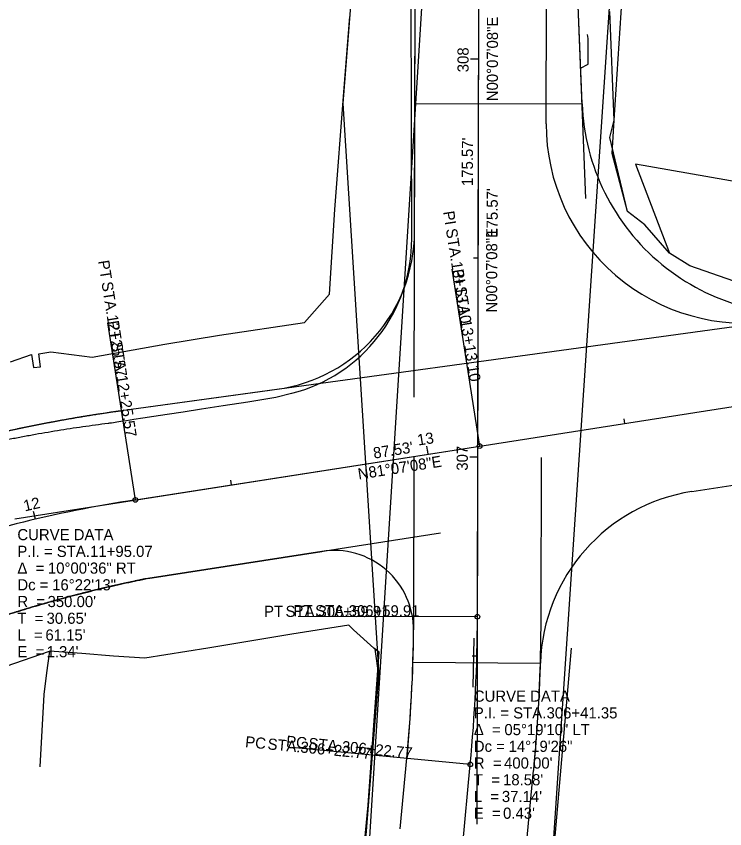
# Model space of a CAD drawing. Extents: x 219353 to 221640, y 361458 to 364236.
# Drawn here: x 220456 to 220633.9, y 362065.1 to 362269.2 of the extents above; entities that cross this region are included whole.
import ezdxf

# ---------------------------------------------------------------- set-up
doc = ezdxf.new("R2010")
doc.units = 0
for name, color, linetype in [('Default', 7, 'Continuous'), ('DR_P_Cells', 7, 'Continuous'), ('DR_P_GenericNode', 7, 'Continuous'), ('DR_X_Cells', 7, 'Continuous'), ('DR_X_GenericNode', 7, 'Continuous'), ('DR_X_Storm_Sewer', 7, 'Continuous'), ('DT_X_Contour_Major', 7, 'Continuous'), ('DT_X_Contour_Minor', 7, 'Continuous'), ('DT_X_Terrain_Boundary', 7, 'Continuous'), ('SC_ProfileRun1', 7, 'Continuous'), ('SC_ProfileRun2', 7, 'Continuous'), ('SC_ProfileRun3', 7, 'Continuous'), ('SC_Scratch1', 7, 'Continuous'), ('UT_X_San_Storm_Line', 7, 'Continuous'), ('UT_X_Sanitary_Cells', 7, 'Continuous')]:
    doc.layers.add(name, color=color, linetype=linetype)

msp = doc.modelspace()

# ---------------------------------------------------------------- linework, layer by layer
at = {"layer": 'Default'}
for p, q in [((220606.11, 362243.12), (220684.52, 363442.47)), ((220589.94, 362047.45), (220608.12, 362317.78)), ((220605.68, 362234.69), (220606.11, 362243.12)), ((220609.47, 362220.11), (220605.68, 362234.69)), ((220718.01, 362213.16), (220611.49, 362232.06)), ((220611.49, 362232.06), (220620.05, 362209.64)), ((220613.84, 362216.77), (220609.47, 362220.11)), ((220620.05, 362209.64), (220613.84, 362216.77))]:
    msp.add_line(p, q, dxfattribs=at)
for points in [[(220418.89, 362155.61), (220419.93, 362155.94), (220422, 362156.61), (220425.12, 362157.57), (220428.25, 362158.5), (220431.39, 362159.41), (220434.53, 362160.29), (220437.68, 362161.14), (220440.84, 362161.96), (220444, 362162.76), (220447.17, 362163.53), (220450.35, 362164.27), (220453.53, 362164.98), (220456.72, 362165.67), (220459.91, 362166.33), (220463.11, 362166.95), (220466.31, 362167.56), (220469.52, 362168.13), (220472.73, 362168.67), (220475.95, 362169.19), (220479.17, 362169.68), (220481.32, 362169.98), (220482.39, 362170.13)], [(220488.46, 362127.86), (220487.52, 362127.67), (220485.66, 362127.29), (220482.86, 362126.68), (220480.08, 362126.06), (220477.3, 362125.41), (220474.52, 362124.73), (220471.76, 362124.03), (220469, 362123.31), (220466.25, 362122.57), (220463.5, 362121.8), (220460.77, 362121.01), (220458.04, 362120.19), (220455.32, 362119.35), (220452.61, 362118.49), (220449.91, 362117.61), (220447.21, 362116.7), (220444.53, 362115.77), (220441.85, 362114.81), (220439.18, 362113.84), (220436.53, 362112.84), (220434.76, 362112.15), (220433.88, 362111.81)]]:
    msp.add_open_spline(points, degree=3, dxfattribs=at)
at = {"layer": 'DR_X_Cells'}
for p, q in [((220572.38, 362161.22), (220565.44, 362205.68)), ((220485.9, 362147.7), (220478.95, 362192.16)), ((220571.8, 362118.35), (220526.8, 362118.44)), ((220570.01, 362081.26), (220525.21, 362085.53))]:
    msp.add_line(p, q, dxfattribs=at)
for centre in [(220572.38, 362161.22), (220485.9, 362147.7), (220571.8, 362118.35), (220570.01, 362081.26)]:
    msp.add_circle(centre, 0.6, dxfattribs=at)
at = {"layer": 'DR_X_GenericNode'}
for p, q in [((220631.67, 363446.41), (220538.01, 362247.29)), ((220541.47, 362010.88), (220631.67, 363446.41)), ((220555.31, 362213.3), (220555.17, 362293.95)), ((220589.06, 362242.18), (220589.17, 362293.88)), ((220606.11, 362243.12), (220605.04, 362270.37)), ((220538.01, 362247.29), (220547.06, 362103.67)), ((220605.08, 362238.74), (220606.11, 362243.12)), ((220609.47, 362220.11), (220605.08, 362238.74)), ((220613.84, 362216.77), (220609.47, 362220.11)), ((220620.05, 362209.64), (220613.84, 362216.77)), ((220625.13, 362206.46), (220620.05, 362209.64)), ((220636.18, 362202.62), (220625.13, 362206.46)), ((220521.18, 362173.46), (220525.15, 362174.47)), ((220625.65, 362149.8), (220725.47, 362165.4)), ((220532.69, 362134.77), (220488.99, 362127.94)), ((220547.06, 362103.67), (220546.11, 362110.22)), ((220589.94, 362047.45), (220595.41, 362110.45)), ((220547.06, 362103.67), (220546.95, 362107.22)), ((220543.46, 362058.41), (220547.06, 362103.67)), ((220552.39, 362065.09), (220554.08, 362082.78)), ((220584.25, 362062.06), (220585.93, 362079.75))]:
    msp.add_line(p, q, dxfattribs=at)
for centre, radius, start, end in [((220639.06, 362242.08), 50, 179.8811, 278.8811), ((220515.31, 362213.24), 40, 284.2423, 0.0978), ((220632.6, 362105.34), 45, 98.8811, 178.2805), ((220535.78, 362115.01), 20, 359.3445, 98.8811), ((220539.93, 361801.9), 330, 98.8811, 98.9741), ((220171.81, 362119.18), 384, 354.5615, 359.3445), ((220171.81, 362119.18), 416, 354.5615, 358.2805)]:
    msp.add_arc(centre, radius, start, end, dxfattribs=at)
msp.add_open_spline([(220419.33, 362154.32), (220420.36, 362154.62), (220422.43, 362155.24), (220425.53, 362156.12), (220428.63, 362156.98), (220431.75, 362157.81), (220434.87, 362158.61), (220437.99, 362159.39), (220441.12, 362160.14), (220444.26, 362160.86), (220447.4, 362161.56), (220450.54, 362162.22), (220453.69, 362162.86), (220456.85, 362163.47), (220460.01, 362164.06), (220463.17, 362164.61), (220466.34, 362165.14), (220469.51, 362165.64), (220472.68, 362166.12), (220475.86, 362166.56), (220479.03, 362166.98), (220481.16, 362167.24), (220521.18, 362173.46)], degree=3, dxfattribs=at)
at = {"layer": 'DT_X_Contour_Major'}
for p, q in [((220571.7, 362066.21), (220572.38, 362396.56)), ((220571.7, 362066.21), (220572.17, 362293.91)), ((220571.8, 362118.35), (220572.17, 362293.91)), ((220571.8, 362118.35), (220572.17, 362293.91)), ((220572.38, 362161.22), (221144.38, 362250.6)), ((220572.38, 362161.22), (221144.38, 362250.6)), ((220455.61, 362142.97), (220572.38, 362161.22)), ((220485.9, 362147.7), (220572.38, 362161.22)), ((220485.9, 362147.7), (220572.38, 362161.22)), ((220570.71, 362100.69), (220570.95, 362112.98)), ((220552.88, 361901.39), (220570.01, 362081.26))]:
    msp.add_line(p, q, dxfattribs=at)
for centre, radius, start, end in [((220539.93, 361801.9), 350, 98.8811, 108.8911), ((220539.93, 361801.9), 350, 98.8811, 108.8911), ((220171.81, 362119.18), 400, 354.5615, 359.8811), ((220171.81, 362119.18), 400, 354.5615, 359.8811)]:
    msp.add_arc(centre, radius, start, end, dxfattribs=at)
at = {"layer": 'DT_X_Contour_Minor'}
for p, q in [((220482.39, 362170.13), (221640, 362328.87)), ((220555.92, 362173.47), (220556.17, 362293.95)), ((220555.92, 362173.47), (220556.17, 362293.95)), ((220556.01, 362215.03), (220556.17, 362293.95)), ((220556.01, 362215.03), (220556.17, 362293.95)), ((220556.01, 362215.03), (220556.17, 362293.95)), ((220599.02, 362223.38), (220596.25, 362293.86)), ((220598.09, 362247.17), (220596.25, 362293.86)), ((220598.09, 362247.17), (220596.25, 362293.86)), ((220556.07, 362247.25), (220598.09, 362247.17)), ((220571.8, 362118.35), (220572.07, 362247.22)), ((220482.39, 362170.13), (220521.44, 362175.49)), ((220482.39, 362170.13), (220521.44, 362175.49)), ((220482.39, 362170.13), (220521.44, 362175.49)), ((220482.39, 362170.13), (220519.63, 362175.24)), ((220625.65, 362149.8), (220725.47, 362165.4)), ((220625.65, 362149.8), (220725.47, 362165.4)), ((220555.8, 362118.38), (220555.89, 362158.44)), ((220555.8, 362118.38), (220555.89, 362158.44)), ((220587.8, 362118.31), (220587.89, 362158.38)), ((220587.8, 362118.31), (220587.89, 362158.38)), ((220488.99, 362127.94), (220562.52, 362139.43)), ((220488.99, 362127.94), (220532.69, 362134.77)), ((220532.69, 362134.77), (220488.99, 362127.94)), ((220378.74, 362079.82), (220464.36, 362109.73)), ((220555.61, 362106.94), (220587.62, 362106.69)), ((220552.39, 362065.09), (220554.08, 362082.78)), ((220552.39, 362065.09), (220554.08, 362082.78)), ((220552.39, 362065.09), (220554.08, 362082.78)), ((220552.39, 362065.09), (220554.08, 362082.78)), ((220584.25, 362062.06), (220585.93, 362079.75)), ((220584.25, 362062.06), (220585.93, 362079.75)), ((220584.25, 362062.06), (220585.93, 362079.75)), ((220584.25, 362062.06), (220585.93, 362079.75))]:
    msp.add_line(p, q, dxfattribs=at)
for points in [[(220454.55, 362182.38), (220459.81, 362184.23), (220460.35, 362180.94), (220462.07, 362181.12), (220461.66, 362184.35), (220464.67, 362184.89), (220475.07, 362183.58), (220493.27, 362186.84), (220507.06, 362189.07), (220528.39, 362192.25), (220534.64, 362199.36), (220536.02, 362220.62), (220538.22, 362250.11), (220539.75, 362269.08)], [(220542.63, 362052.8), (220544.35, 362071.05), (220545.67, 362089.98), (220547.11, 362109.41), (220545.79, 362110.48), (220540.64, 362115.08), (220539.5, 362116.23), (220525.19, 362113.93), (220504.07, 362110.45), (220488.27, 362107.93), (220480.39, 362108.46), (220472.41, 362109.12), (220464.36, 362109.73), (220463.61, 362104.26), (220462.9, 362098.83), (220461.92, 362080.65)]]:
    msp.add_lwpolyline(points, dxfattribs=at)
for centre, radius, start, end in [((220653.05, 362249.33), 55, 182.2506, 278.8811), ((220653.05, 362249.33), 55, 182.2506, 278.8811), ((220516.01, 362215.12), 40, 277.8079, 359.8811), ((220516.01, 362215.12), 40, 277.8079, 359.8811), ((220516.01, 362215.12), 40, 277.8079, 359.8811), ((220632.6, 362105.34), 45, 98.8811, 178.2805), ((220632.6, 362105.34), 45, 98.8811, 178.2805), ((220535.78, 362115.01), 20, 359.3445, 98.8811), ((220535.78, 362115.01), 20, 359.3445, 98.8811), ((220539.93, 361801.9), 330, 98.8811, 98.9741), ((220539.93, 361801.9), 330, 98.8811, 98.9741), ((220539.93, 361801.9), 330, 98.8811, 98.9741), ((220171.81, 362119.18), 384, 354.5615, 359.8811), ((220171.81, 362119.18), 384, 354.5615, 359.8811), ((220171.81, 362119.18), 400, 358.2296, 359.8811), ((220171.81, 362119.18), 416, 354.5615, 359.8811), ((220171.81, 362119.18), 416, 354.5615, 359.8811), ((220171.81, 362119.18), 384, 354.5615, 359.3445), ((220171.81, 362119.18), 384, 354.5615, 359.3445), ((220171.81, 362119.18), 416, 354.5615, 358.2805), ((220171.81, 362119.18), 416, 354.5615, 358.2805)]:
    msp.add_arc(centre, radius, start, end, dxfattribs=at)
for points in [[(220418.89, 362155.61), (220419.93, 362155.94), (220422, 362156.61), (220425.12, 362157.57), (220428.25, 362158.5), (220431.39, 362159.41), (220434.53, 362160.29), (220437.68, 362161.14), (220440.84, 362161.96), (220444, 362162.76), (220447.17, 362163.53), (220450.35, 362164.27), (220453.53, 362164.98), (220456.72, 362165.67), (220459.91, 362166.33), (220463.11, 362166.95), (220466.31, 362167.56), (220469.52, 362168.13), (220472.73, 362168.67), (220475.95, 362169.19), (220479.17, 362169.68), (220481.32, 362169.98), (220482.39, 362170.13)], [(220418.89, 362155.61), (220419.93, 362155.94), (220422, 362156.61), (220425.12, 362157.57), (220428.25, 362158.5), (220431.39, 362159.41), (220434.53, 362160.29), (220437.68, 362161.14), (220440.84, 362161.96), (220444, 362162.76), (220447.17, 362163.53), (220450.35, 362164.27), (220453.53, 362164.98), (220456.72, 362165.67), (220459.91, 362166.33), (220463.11, 362166.95), (220466.31, 362167.56), (220469.52, 362168.13), (220472.73, 362168.67), (220475.95, 362169.19), (220479.17, 362169.68), (220481.32, 362169.98), (220482.39, 362170.13)], [(220418.89, 362155.61), (220419.93, 362155.94), (220422, 362156.61), (220425.12, 362157.57), (220428.25, 362158.5), (220431.39, 362159.41), (220434.53, 362160.29), (220437.68, 362161.14), (220440.84, 362161.96), (220444, 362162.76), (220447.17, 362163.53), (220450.35, 362164.27), (220453.53, 362164.98), (220456.72, 362165.67), (220459.91, 362166.33), (220463.11, 362166.95), (220466.31, 362167.56), (220469.52, 362168.13), (220472.73, 362168.67), (220475.95, 362169.19), (220479.17, 362169.68), (220481.32, 362169.98), (220482.39, 362170.13)], [(220418.89, 362155.61), (220419.93, 362155.94), (220422, 362156.61), (220425.12, 362157.57), (220428.25, 362158.5), (220431.39, 362159.41), (220434.53, 362160.29), (220437.68, 362161.14), (220440.84, 362161.96), (220444, 362162.76), (220447.17, 362163.53), (220450.35, 362164.27), (220453.53, 362164.98), (220456.72, 362165.67), (220459.91, 362166.33), (220463.11, 362166.95), (220466.31, 362167.56), (220469.52, 362168.13), (220472.73, 362168.67), (220475.95, 362169.19), (220479.17, 362169.68), (220481.32, 362169.98), (220482.39, 362170.13)], [(220433.88, 362111.81), (220434.76, 362112.15), (220436.53, 362112.84), (220439.18, 362113.84), (220441.85, 362114.81), (220444.53, 362115.77), (220447.21, 362116.7), (220449.91, 362117.61), (220452.61, 362118.49), (220455.32, 362119.35), (220458.04, 362120.19), (220460.77, 362121.01), (220463.5, 362121.8), (220466.25, 362122.57), (220469, 362123.31), (220471.76, 362124.03), (220474.52, 362124.73), (220477.3, 362125.41), (220480.08, 362126.06), (220482.86, 362126.68), (220485.66, 362127.29), (220487.52, 362127.67), (220488.46, 362127.86)], [(220488.46, 362127.86), (220487.52, 362127.67), (220485.66, 362127.29), (220482.86, 362126.68), (220480.08, 362126.06), (220477.3, 362125.41), (220474.52, 362124.73), (220471.76, 362124.03), (220469, 362123.31), (220466.25, 362122.57), (220463.5, 362121.8), (220460.77, 362121.01), (220458.04, 362120.19), (220455.32, 362119.35), (220452.61, 362118.49), (220449.91, 362117.61), (220447.21, 362116.7), (220444.53, 362115.77), (220441.85, 362114.81), (220439.18, 362113.84), (220436.53, 362112.84), (220434.76, 362112.15), (220433.88, 362111.81)]]:
    msp.add_open_spline(points, degree=3, dxfattribs=at)
at = {"layer": 'DT_X_Terrain_Boundary'}
for p, q in [((220599.61, 362263.63), (220599.47, 362264.63)), ((220599.61, 362263.63), (220599.47, 362264.63)), ((220599.59, 362257.13), (220599.61, 362263.63)), ((220599.59, 362257.13), (220599.61, 362263.63)), ((220597.73, 362256.14), (220599.59, 362257.13)), ((220597.73, 362256.14), (220599.59, 362257.13))]:
    msp.add_line(p, q, dxfattribs=at)
at = {"layer": 'SC_ProfileRun2'}
for p, q in [((220572.38, 362161.22), (220565.44, 362205.68)), ((220485.9, 362147.7), (220478.95, 362192.16)), ((220571.8, 362118.35), (220526.8, 362118.44)), ((220570.01, 362081.26), (220525.21, 362085.53))]:
    msp.add_line(p, q, dxfattribs=at)
for centre in [(220572.38, 362161.22), (220485.9, 362147.7), (220571.8, 362118.35), (220570.01, 362081.26)]:
    msp.add_circle(centre, 0.6, dxfattribs=at)
at = {"layer": 'SC_ProfileRun3'}
for p, q in [((220572.1, 362258.44), (220570.9, 362258.44)), ((220559.44, 362159.19), (220559.25, 362160.38)), ((220571.89, 362158.44), (220570.69, 362158.44)), ((220460.8, 362142.84), (220460.53, 362144))]:
    msp.add_line(p, q, dxfattribs=at)
at = {"layer": 'UT_X_San_Storm_Line'}
for p, q in [((220556.01, 362215.03), (220556.07, 362247.25)), ((220482.39, 362170.13), (220521.44, 362175.49)), ((220625.65, 362149.8), (220725.47, 362165.4)), ((220532.69, 362134.77), (220488.99, 362127.94))]:
    msp.add_line(p, q, dxfattribs=at)
for centre, radius, start, end in [((220653.05, 362249.33), 55, 182.2506, 278.8811), ((220516.01, 362215.12), 40, 277.8079, 359.8811), ((220632.6, 362105.34), 45, 98.8811, 178.2805), ((220535.78, 362115.01), 20, 359.3445, 98.8811), ((220539.93, 361801.9), 330, 98.8811, 98.9741), ((220171.81, 362119.18), 384, 358.1743, 359.3445), ((220171.81, 362119.18), 416, 358.2796, 358.2805)]:
    msp.add_arc(centre, radius, start, end, dxfattribs=at)
for points in [[(220418.89, 362155.61), (220419.48, 362155.8), (220421.52, 362156.46), (220425.24, 362157.6), (220428.2, 362158.49), (220431.38, 362159.41), (220434.51, 362160.28), (220437.66, 362161.13), (220440.82, 362161.96), (220443.98, 362162.76), (220447.15, 362163.52), (220450.32, 362164.26), (220453.51, 362164.98), (220456.69, 362165.66), (220459.89, 362166.32), (220463.09, 362166.95), (220466.3, 362167.55), (220469.49, 362168.12), (220472.76, 362168.68), (220475.81, 362169.17), (220479.66, 362169.75), (220481.78, 362170.05), (220482.39, 362170.13)], [(220488.46, 362127.86), (220487.93, 362127.75), (220486.1, 362127.38), (220482.77, 362126.66), (220480.13, 362126.07), (220477.32, 362125.41), (220474.57, 362124.74), (220471.8, 362124.05), (220469.05, 362123.33), (220466.3, 362122.58), (220463.55, 362121.81), (220460.82, 362121.02), (220458.09, 362120.21), (220455.37, 362119.37), (220452.65, 362118.51), (220449.95, 362117.62), (220447.25, 362116.71), (220444.57, 362115.78), (220441.84, 362114.81), (220439.31, 362113.88), (220436.12, 362112.69), (220434.38, 362112.01), (220433.88, 362111.81)]]:
    msp.add_open_spline(points, degree=2, dxfattribs=at)
at = {"layer": 'UT_X_Sanitary_Cells'}
for p, q in [((220572.1, 362258.44), (220570.1, 362258.44)), ((220571.99, 362208.44), (220570.79, 362208.44)), ((220608.84, 362166.91), (220608.65, 362168.1)), ((220559.44, 362159.19), (220559.13, 362161.17)), ((220571.89, 362158.44), (220569.89, 362158.44)), ((220510.04, 362151.47), (220509.85, 362152.66)), ((220460.8, 362142.84), (220460.35, 362144.78)), ((220571.66, 362108.44), (220570.46, 362108.47))]:
    msp.add_line(p, q, dxfattribs=at)

# ---------------------------------------------------------------- texts
at = {"layer": 'DR_P_Cells'}
for s, rotation, p in [("175.57'", 89.8811, (220576.9, 362213.81)), ("87.53'", 8.8811, (220545.85, 362158.05))]:
    msp.add_text(s, height=2.8, rotation=rotation, dxfattribs=at).set_placement(p)
at = {"layer": 'DR_P_GenericNode'}
for s, rotation, p in [("175.57'", 89.8811, (220570.67, 362226.53)), ("87.53'", 8.8811, (220545.85, 362158.05))]:
    msp.add_text(s, height=2.8, rotation=rotation, dxfattribs=at).set_placement(p)
at = {"layer": 'DR_X_Cells'}
for s, rotation, p in [('PI', 278.8811, (220565.51, 362205.46)), (' STA. ', 278.8811, (220566.04, 362202.11)), ('PT', 278.8811, (220478.94, 362192.52)), ('13+13.10', 278.8811, (220567.49, 362192.77)), (' STA. ', 278.8811, (220479.62, 362188.16)), ('12+25.57', 278.8811, (220481.08, 362178.82)), ('PT', 359.8811, (220525.6, 362118.48)), (' STA. ', 359.8811, (220530.01, 362118.47)), ('306+59.91', 359.8811, (220539.46, 362118.45)), ('PC', 354.5615, (220523.66, 362085.72)), (' STA. ', 354.5615, (220528.22, 362085.28)), ('306+22.77', 354.5615, (220537.63, 362084.39))]:
    msp.add_text(s, height=2.8, rotation=rotation, dxfattribs=at).set_placement(p)
at = {"layer": 'DR_X_Storm_Sewer'}
for s, p in [('CURVE DATA', (220456.26, 362137.57)), ('P.I. = STA. ', (220456.26, 362133.37)), ('11+95.07', (220474.52, 362133.37)), ('Δ  = ', (220456.26, 362129.17)), ('10°00\'36" RT', (220463.93, 362129.17)), ('Dc = ', (220456.26, 362124.97)), ('16°22\'13"', (220464.99, 362124.97)), ('R  = ', (220456.26, 362120.77)), ("350.00'", (220463.84, 362120.77)), ('T  = ', (220456.26, 362116.57)), ("30.65'", (220463.59, 362116.57)), ('L  = ', (220456.26, 362112.37)), ("61.15'", (220463.3, 362112.37)), ('E  = ', (220456.26, 362108.17)), ("1.34'", (220463.6, 362108.17)), ('CURVE DATA', (220570.9, 362097)), ('P.I. = STA. ', (220570.9, 362092.8)), ('306+41.35', (220589.17, 362092.8)), ('Δ  = ', (220570.9, 362088.6)), ('05°19\'10" LT', (220578.58, 362088.6)), ('Dc = ', (220570.9, 362084.4)), ('14°19\'26"', (220579.64, 362084.4)), ('R  = ', (220570.9, 362080.2)), ("400.00'", (220578.49, 362080.2)), ('T  = ', (220570.9, 362076)), ("18.58'", (220578.24, 362076)), ('L  = ', (220570.9, 362071.8)), ("37.14'", (220577.95, 362071.8)), ('E  = ', (220570.9, 362067.6)), ("0.43'", (220578.25, 362067.6))]:
    msp.add_text(s, height=2.8, dxfattribs=at).set_placement(p)
at = {"layer": 'SC_ProfileRun1'}
for s, rotation, p in [('N00°07\'08"E', 89.8811, (220576.94, 362247.84)), ('N81°07\'08"E', 8.8811, (220542, 362152.78))]:
    msp.add_text(s, height=2.8, rotation=rotation, dxfattribs=at).set_placement(p)
at = {"layer": 'SC_ProfileRun2'}
for s, rotation, p in [('PI', 278.8811, (220563.19, 362220.06)), (' STA. ', 278.8811, (220563.71, 362216.7)), ('PT', 278.8811, (220476.52, 362207.69)), ('13+13.10', 278.8811, (220565.17, 362207.37)), (' STA. ', 278.8811, (220477.21, 362203.33)), ('12+25.57', 278.8811, (220478.67, 362193.99)), ('PT', 359.8811, (220518.22, 362118.31)), (' STA. ', 359.8811, (220522.57, 362118.31)), ('306+59.91', 359.8811, (220531.89, 362118.29)), ('PC', 354.5615, (220513.38, 362085.58)), (' STA. ', 354.5615, (220517.96, 362085.14)), ('306+22.77', 354.5615, (220527.24, 362084.26))]:
    msp.add_text(s, height=2.8, rotation=rotation, dxfattribs=at).set_placement(p)
at = {"layer": 'SC_Scratch1'}
for s, rotation, p in [('N00°07\'08"E', 89.8811, (220576.76, 362194.76)), ('N81°07\'08"E', 8.8811, (220542, 362152.79))]:
    msp.add_text(s, height=2.8, rotation=rotation, dxfattribs=at).set_placement(p)
at = {"layer": 'UT_X_Sanitary_Cells'}
for s, rotation, p in [('308', 89.8811, (220569.59, 362255.11)), ('13', 8.8811, (220556.92, 362161.33)), ('307', 89.8811, (220569.38, 362155.03)), ('12', 13.0667, (220458.13, 362144.78))]:
    msp.add_text(s, height=2.8, rotation=rotation, dxfattribs=at).set_placement(p)

doc.saveas('drawing.dxf')
